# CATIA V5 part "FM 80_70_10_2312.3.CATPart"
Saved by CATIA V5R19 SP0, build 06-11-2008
Part number: FM 80_70_10_2312.3
Definition: FM 80_70_10_2312
Nomenclature: FM 80_70_10_2312
Source: Unknown
Description: PART-FM 80_70_10_2312-DESC
Bounding box of the stored display mesh (mm): x -35 to 35, y -35 to 35, z -40 to -30
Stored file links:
  C:\Users\jsmid\Desktop\DP_Smidak_Forma LEGO\FM 80_70_10_2312.3.CATPart
  C:\Users\jsmid\Desktop\Forma_kostka\Part1.CATPart
  C:\Users\jsmid\Desktop\Forma_kostka\FM 85_70_10_2312.CATPart
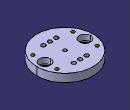
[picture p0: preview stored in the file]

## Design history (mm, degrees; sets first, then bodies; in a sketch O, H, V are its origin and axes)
Body1 "FM 80_70_10_2312" (main body)
  Solid1: solid without history
  DatumCurve1 to DatumCurve3
  Sketch1 on face of Solid1, origin (0, 0, -30), H (1, 0, 0), V (0, 1, 0)
    circle A1 centre (-8.04, 18.939) radius 2.25
    circle A2 centre (0, 18.939) radius 2.25
    point P2 (0, 18.939)
    circle A3 centre (8.04, 18.939) radius 2.25
    reference projected circle E1 centre (8.04, 18.939) radius 2.25 from edge of DatumCurve1
    reference projected circle E2 centre (0, 18.939) radius 2.25 from edge of DatumCurve2
    reference projected circle E3 centre (-8.04, 18.939) radius 2.25 from edge of DatumCurve3
    distance A3 E1 = 0
    radius A3 = 2.25
    radius A3 = 2.25 (reference)
    distance A2 E2 = 0
    radius A2 = 2.25
    distance A1 E3 = 0
    radius A1 = 2.25
    coincidence: P2 V
  Pocket1: profile Sketch1, direction (0, 0, -1), through (limit type 6)
  Mirror1: of Pocket1, about zx-plane
  Sketch2 on face of Solid1, origin (0, 0, -30), H (1, 0, 0), V (0, 1, 0)
    circle A1 centre (0, 18.939) radius 2.5
    point P1 (0, 18.939)
    reference projected circle E1 centre (0, 18.939) radius 2.25 from Sketch1.A2
    circle A2 centre (8.04, 18.939) radius 2.5
    reference projected circle E2 centre (8.04, 18.939) radius 2.25 from Sketch1.A3
    circle A3 centre (-8.04, 18.939) radius 2.5
    reference projected circle E3 centre (-8.04, 18.939) radius 2.25 from Sketch1.A1
    radius A1 = 2.5
    distance A1 E1 = 0.25
    radius A2 = 2.5
    distance A2 E2 = 0.25
    radius A3 = 2.5
    distance A3 E3 = 0.25
    coincidence: P1 V
  Pocket2: profile Sketch2, direction (0, 0, -1), through (limit type 6)
  Mirror2: of Pocket2, about zx-plane
  Sketch3 on face of Solid1, origin (0, 0, -40), H (1, 0, 0), V (0, 1, 0)
    construction line L1 (-8.5, 18.9) -> (8.5, 18.9)
    point P1 (-8.5, 18.9)
    line L2 (-8.5, 23.2) -> (8.5, 23.2)
    line L3 (8.5, 14.6) -> (-8.5, 14.6)
    arc A1 centre (8.5, 18.9) radius 4.3 from (8.5, 23.2) to (8.5, 14.6) cw
    arc A2 centre (-8.5, 18.9) radius 4.3 from (-8.5, 14.6) to (-8.5, 23.2) cw
    distance L1 L2 = 4.3
    distance L1 H = 18.9
    length L1 = 17
    distance P1 V = 8.5
    horizontal: L1 H
    tangency: A1 L2, A2 L2, A1 L3, A2 L3
  Pocket3: profile Sketch3, direction (0, 0, 1), length 3
  Mirror3: of Pocket3, about zx-plane
  Sketch4 on face of Solid1, origin (0, 0, -40), H (1, 0, 0), V (0, -1, 0)
    circle A1 centre (0, 0) radius 4.25
    radius A1 = 4.25
  Pocket4: profile Sketch4, direction (0, 0, 1), length 3
  Sketch5 on end face of Pocket4, origin (0, 0, -37), H (1, 0, 0), V (0, -1, 0)
    circle A1 centre (0, 0) radius 2.25
    radius A1 = 2.25
  Pocket5: profile Sketch5, direction (0, 0, 1), through (limit type 6)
